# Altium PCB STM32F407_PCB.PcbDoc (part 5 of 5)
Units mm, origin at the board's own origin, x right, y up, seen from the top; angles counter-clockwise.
Board outline 100.27 x 100.27 mm, 2 copper layers (Top Layer, Bottom Layer); 134 components, 132 nets, 659 pads, 288 vias.
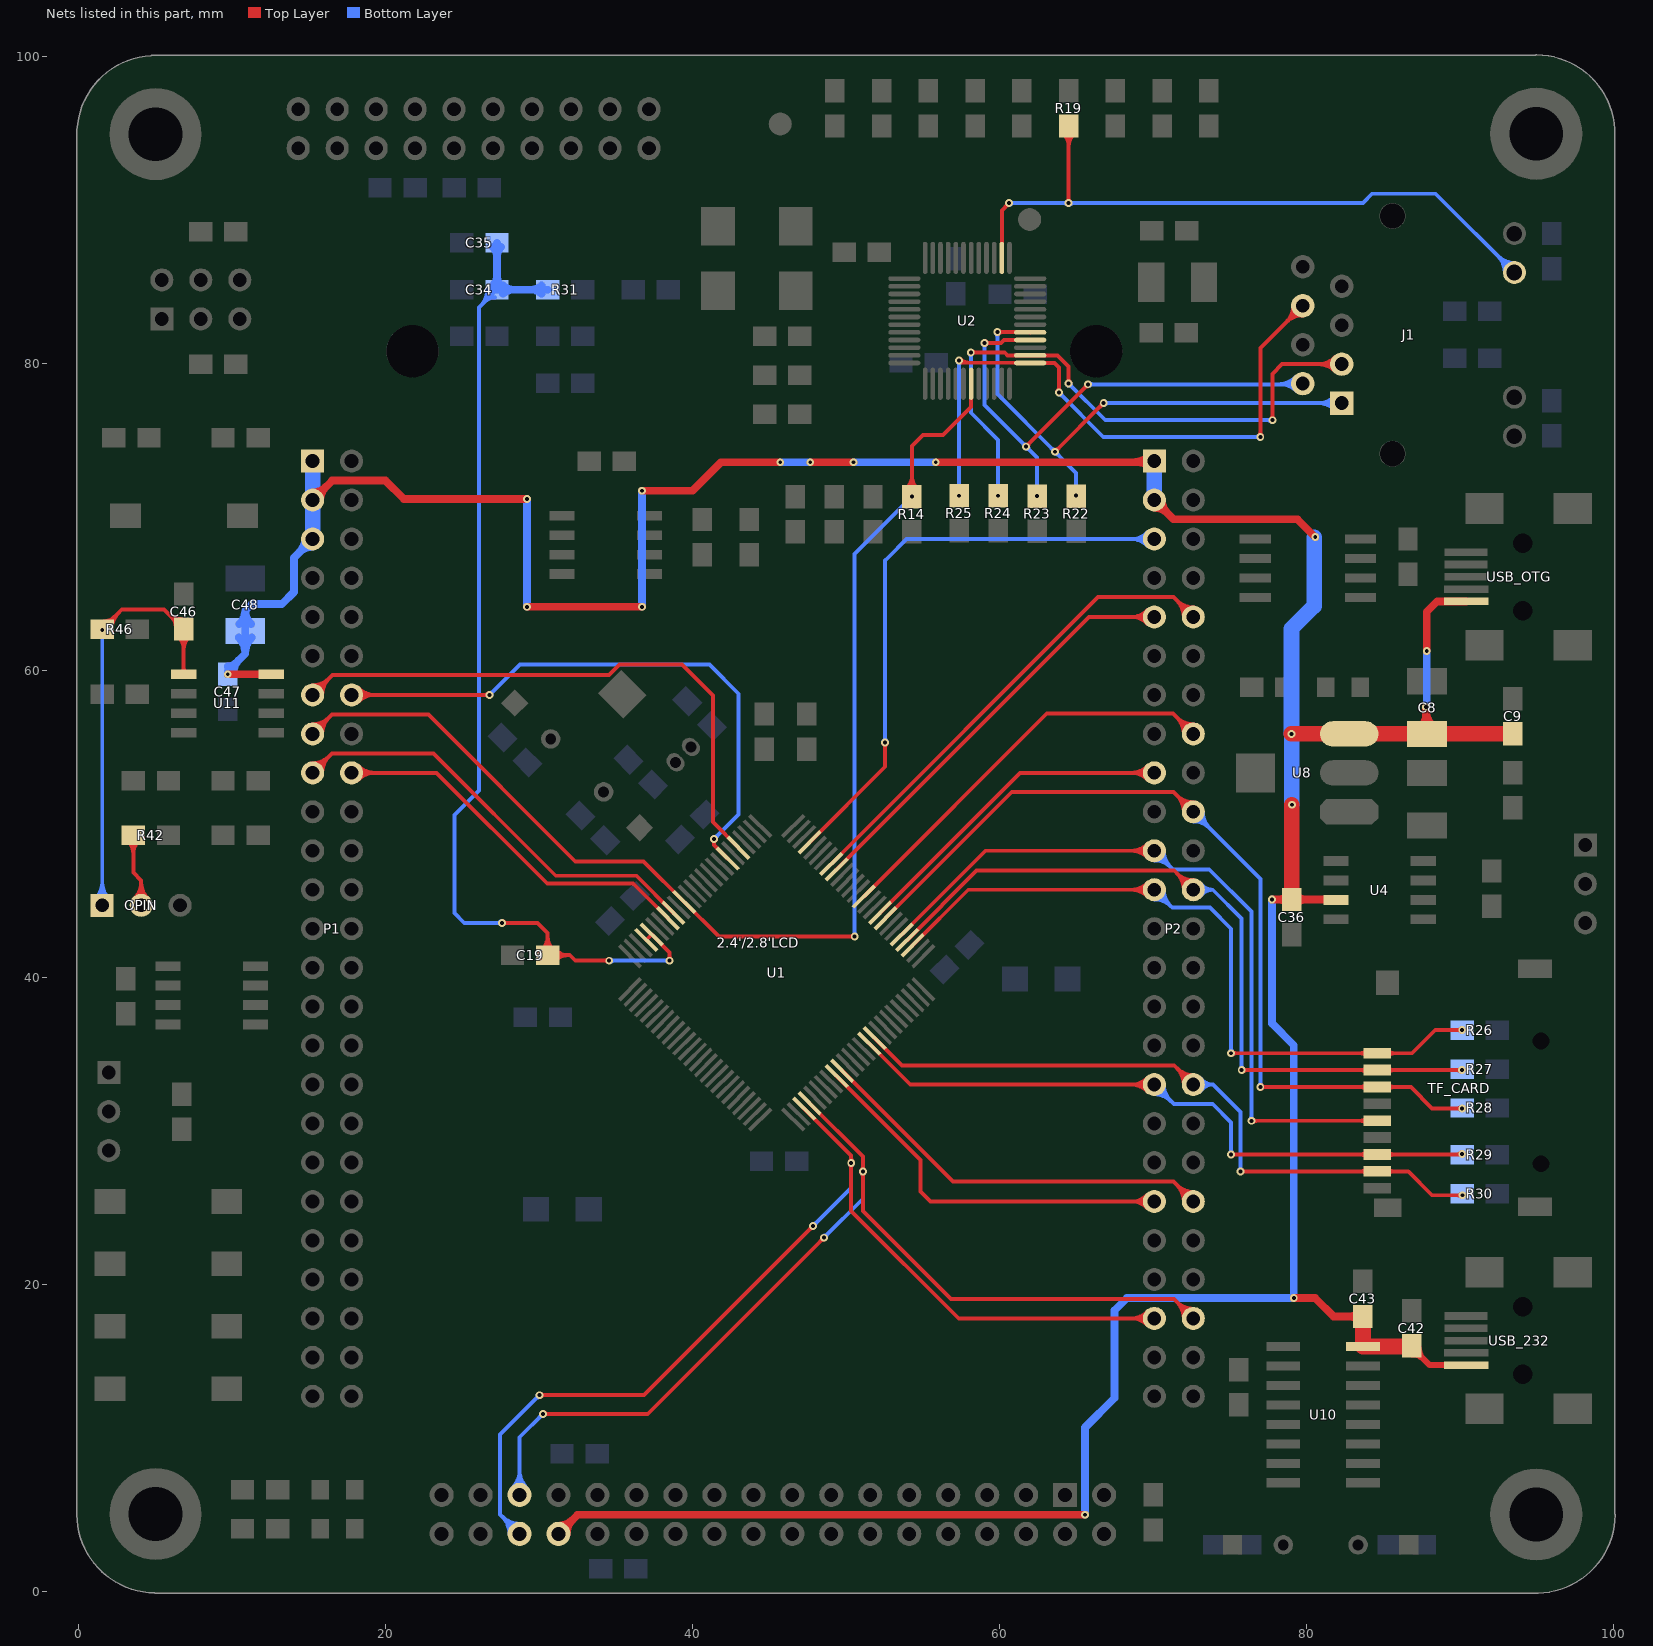
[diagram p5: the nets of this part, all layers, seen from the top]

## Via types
v1: diameter 0.508, hole 0.254, Top Layer to Bottom Layer, 288 vias

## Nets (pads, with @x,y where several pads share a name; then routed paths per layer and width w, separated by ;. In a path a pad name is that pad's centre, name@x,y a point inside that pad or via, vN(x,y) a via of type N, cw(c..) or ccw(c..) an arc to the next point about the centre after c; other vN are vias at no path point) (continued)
PB6: P2.9 U1.92 | length 35
  Top Layer w0.254: U1.92@49.398,47.045 65.853,63.5 P2.9@70.104,63.5 ; 68.6,63.5 cw(c68.6,61.996) 69.663,63.059 ccw(c68.6,61.996) 68.6,63.5 ; 68.6,63.5 ccw(c68.6,65.004) 69.663,63.941 cw(c68.6,65.004) 68.6,63.5 ; 69.213,63.5 cw(c69.213,62.609) 69.843,63.239 ccw(c69.213,62.609) 69.213,63.5 ; 69.213,63.5 ccw(c69.213,64.391) 69.843,63.761 cw(c69.213,64.391) 69.213,63.5
PB7: P2.10 U1.93 | length 38.9
  Top Layer w0.254: U1.93@49.045,47.399 66.441,64.795 71.349,64.795 P2.10@72.644,63.5 ; 71.58,64.564 cw(c70.517,63.5) 72.021,63.5 ccw(c70.517,63.5) 71.58,64.564 ; 71.58,64.564 ccw(c72.644,65.627) 72.644,64.123 cw(c72.644,65.627) 71.58,64.564 ; 72.014,64.13 cw(c71.384,63.5) 72.275,63.5 ccw(c71.384,63.5) 72.014,64.13 ; 72.014,64.13 ccw(c72.644,64.76) 72.644,63.869 cw(c72.644,64.76) 72.014,64.13
PB14: 2.4'/2.8'LCD.30 P2.45 U1.53 | length 91.1
  Top Layer w0.254: v1(30.023,12.776) 36.83,12.776 v1(47.854,23.8) ; U1.53@47.277,31.453 50.343,28.387 v1(50.343,27.915) 50.343,24.79 57.353,17.78 P2.45@70.104,17.78 ; 30.329,12.776 cw(c30.329,13.083) 30.113,12.866 ccw(c30.329,13.083) 30.329,12.776 ; 30.329,12.776 ccw(c30.329,12.47) 30.113,12.686 cw(c30.329,12.47) 30.329,12.776 ; 47.637,23.583 cw(c47.854,23.366) 47.854,23.673 ccw(c47.854,23.366) 47.637,23.583 ; 47.637,23.583 ccw(c47.42,23.8) 47.727,23.8 cw(c47.42,23.8) 47.637,23.583 ; 50.343,27.608 cw(c50.649,27.608) 50.433,27.825 ccw(c50.649,27.608) 50.343,27.608 ; 50.343,27.608 ccw(c50.036,27.608) 50.253,27.825 cw(c50.036,27.608) 50.343,27.608 ; 50.343,28.221 cw(c50.036,28.221) 50.253,28.004 ccw(c50.036,28.221) 50.343,28.221 ; 50.343,28.221 ccw(c50.649,28.221) 50.433,28.004 cw(c50.649,28.221) 50.343,28.221 ; 68.6,17.78 cw(c68.6,16.276) 69.663,17.339 ccw(c68.6,16.276) 68.6,17.78 ; 68.6,17.78 ccw(c68.6,19.284) 69.663,18.221 cw(c68.6,19.284) 68.6,17.78 ; 69.213,17.78 cw(c69.213,16.889) 69.843,17.519 ccw(c69.213,16.889) 69.213,17.78 ; 69.213,17.78 ccw(c69.213,18.671) 69.843,18.041 cw(c69.213,18.671) 69.213,17.78
  Bottom Layer w0.254: 2.4'/2.8'LCD.30@28.727,3.734 27.457,5.004 27.457,10.211 v1(30.023,12.776) ; v1(47.854,23.8) 50.343,26.289 v1(50.343,27.915) ; 27.6,4.861 cw(c26.473,3.734) 28.067,3.734 ccw(c26.473,3.734) 27.6,4.861 ; 27.6,4.861 ccw(c28.727,5.989) 28.727,4.394 cw(c28.727,5.989) 27.6,4.861 ; 28.034,4.428 cw(c27.34,3.734) 28.321,3.734 ccw(c27.34,3.734) 28.034,4.428 ; 28.034,4.428 ccw(c28.727,5.121) 28.727,4.14 cw(c28.727,5.121) 28.034,4.428 ; 29.806,12.559 cw(c30.023,12.343) 30.023,12.649 ccw(c30.023,12.343) 29.806,12.559 ; 29.806,12.559 ccw(c29.589,12.776) 29.896,12.776 cw(c29.589,12.776) 29.806,12.559 ; 48.07,24.017 cw(c47.854,24.233) 47.854,23.927 ccw(c47.854,24.233) 48.07,24.017 ; 48.07,24.017 ccw(c48.287,23.8) 47.981,23.8 cw(c48.287,23.8) 48.07,24.017 ; 50.343,27.608 cw(c50.649,27.608) 50.433,27.825 ccw(c50.649,27.608) 50.343,27.608 ; 50.343,27.608 ccw(c50.036,27.608) 50.253,27.825 cw(c50.036,27.608) 50.343,27.608
PB15: 2.4'/2.8'LCD.29 P2.46 U1.54 | length 89.6
  Top Layer w0.254: v1(30.251,11.557) 37.084,11.557 v1@48.489,22.962 ; U1.54@47.63,31.807 51.105,28.332 v1(51.105,27.356) 51.105,24.79 56.845,19.05 71.374,19.05 P2.46@72.644,17.78 ; 30.558,11.557 cw(c30.558,11.864) 30.341,11.647 ccw(c30.558,11.864) 30.558,11.557 ; 30.558,11.557 ccw(c30.558,11.25) 30.341,11.467 cw(c30.558,11.25) 30.558,11.557 ; 48.351,22.824 cw(c48.568,22.607) 48.568,22.914 ccw(c48.568,22.607) 48.351,22.824 ; 48.351,22.824 ccw(c48.134,23.041) 48.441,23.041 cw(c48.134,23.041) 48.351,22.824 ; 51.105,27.049 cw(c51.411,27.049) 51.195,27.266 ccw(c51.411,27.049) 51.105,27.049 ; 51.105,27.049 ccw(c50.798,27.049) 51.015,27.266 cw(c50.798,27.049) 51.105,27.049 ; 51.105,27.662 cw(c50.798,27.662) 51.015,27.446 ccw(c50.798,27.662) 51.105,27.662 ; 51.105,27.662 ccw(c51.411,27.662) 51.195,27.446 cw(c51.411,27.662) 51.105,27.662 ; 71.58,18.844 cw(c70.517,17.78) 72.021,17.78 ccw(c70.517,17.78) 71.58,18.844 ; 71.58,18.844 ccw(c72.644,19.907) 72.644,18.403 cw(c72.644,19.907) 71.58,18.844 ; 72.014,18.41 cw(c71.384,17.78) 72.275,17.78 ccw(c71.384,17.78) 72.014,18.41 ; 72.014,18.41 ccw(c72.644,19.04) 72.644,18.149 cw(c72.644,19.04) 72.014,18.41
  Bottom Layer w0.254: 2.4'/2.8'LCD.29@28.727,6.274 28.727,10.033 v1(30.251,11.557) ; v1@48.489,22.962 v1(48.568,23.041) 51.105,25.578 v1(51.105,27.356) ; 28.727,7.255 cw(c27.746,7.255) 28.44,6.561 ccw(c27.746,7.255) 28.727,7.255 ; 28.727,7.255 ccw(c29.709,7.255) 29.015,6.561 cw(c29.709,7.255) 28.727,7.255 ; 28.727,7.868 cw(c27.133,7.868) 28.26,6.741 ccw(c27.133,7.868) 28.727,7.868 ; 28.727,7.868 ccw(c30.322,7.868) 29.194,6.741 cw(c30.322,7.868) 28.727,7.868 ; 30.035,11.34 cw(c30.251,11.123) 30.251,11.43 ccw(c30.251,11.123) 30.035,11.34 ; 30.035,11.34 ccw(c29.818,11.557) 30.124,11.557 cw(c29.818,11.557) 30.035,11.34 ; 48.785,23.258 cw(c48.568,23.475) 48.568,23.168 ccw(c48.568,23.475) 48.785,23.258 ; 48.785,23.258 ccw(c49.002,23.041) 48.695,23.041 cw(c49.002,23.041) 48.785,23.258 ; 51.105,27.049 cw(c51.411,27.049) 51.195,27.266 ccw(c51.411,27.049) 51.105,27.049 ; 51.105,27.049 ccw(c50.798,27.049) 51.015,27.266 cw(c50.798,27.049) 51.105,27.049
PC0: P1.15 R14.2 U1.15 U2.7 | length 97
  Top Layer w0.254: P1.15@15.24,55.88 16.51,57.15 22.784,57.15 32.36,47.574 36.813,47.574 U1.15@39.463,44.924 41.715,42.672 v1(50.571,42.672) ; v1(54.305,71.349) 54.305,74.651 55.016,75.362 56.337,75.362 58.162,77.187 U2.7@58.162,78.704 ; 15.87,56.51 cw(c15.24,57.14) 15.24,56.249 ccw(c15.24,57.14) 15.87,56.51 ; 15.87,56.51 ccw(c16.5,55.88) 15.609,55.88 cw(c16.5,55.88) 15.87,56.51 ; 16.304,56.944 cw(c15.24,58.007) 15.24,56.503 ccw(c15.24,58.007) 16.304,56.944 ; 16.304,56.944 ccw(c17.367,55.88) 15.863,55.88 cw(c17.367,55.88) 16.304,56.944 ; 50.265,42.672 cw(c50.265,42.365) 50.482,42.582 ccw(c50.265,42.365) 50.265,42.672 ; 50.265,42.672 ccw(c50.265,42.979) 50.482,42.762 cw(c50.265,42.979) 50.265,42.672 ; R14.2@54.305,71.655 cw(c53.999,71.655) 54.215,71.438 ccw(c53.999,71.655) R14.2@54.305,71.655 ; R14.2@54.305,71.655 ccw(c54.612,71.655) 54.395,71.438 cw(c54.612,71.655) R14.2@54.305,71.655 ; 54.305,72.702 cw(c53.079,72.702) 53.946,71.835 ccw(c53.079,72.702) 54.305,72.702 ; 54.305,72.702 ccw(c55.532,72.702) 54.664,71.835 cw(c55.532,72.702) 54.305,72.702
  Bottom Layer w0.254: v1(50.571,42.672) 50.571,67.615 v1(54.305,71.349) ; 50.571,42.979 cw(c50.265,42.979) 50.482,42.762 ccw(c50.265,42.979) 50.571,42.979 ; 50.571,42.979 ccw(c50.878,42.979) 50.661,42.762 cw(c50.878,42.979) 50.571,42.979 ; 54.088,71.132 cw(c54.305,70.915) 54.305,71.222 ccw(c54.305,70.915) 54.088,71.132 ; 54.088,71.132 ccw(c53.872,71.349) 54.178,71.349 cw(c53.872,71.349) 54.088,71.132
PC2: P1.17 U1.17 | length 35.9
  Top Layer w0.254: P1.17@15.24,53.34 16.51,54.61 23.114,54.61 31.09,46.634 36.338,46.634 U1.17@38.756,44.217 ; 15.87,53.97 cw(c15.24,54.6) 15.24,53.709 ccw(c15.24,54.6) 15.87,53.97 ; 15.87,53.97 ccw(c16.5,53.34) 15.609,53.34 cw(c16.5,53.34) 15.87,53.97 ; 16.304,54.404 cw(c15.24,55.467) 15.24,53.963 ccw(c15.24,55.467) 16.304,54.404 ; 16.304,54.404 ccw(c17.367,53.34) 15.863,53.34 cw(c17.367,53.34) 16.304,54.404
PC3: P1.18 U1.18 | length 32.1
  Top Layer w0.254: P1.18@17.78,53.34 23.317,53.34 30.531,46.126 36.139,46.126 U1.18@38.403,43.863 ; 18.671,53.34 cw(c18.671,54.231) 18.041,53.601 ccw(c18.671,54.231) 18.671,53.34 ; 18.671,53.34 ccw(c18.671,52.449) 18.041,53.079 cw(c18.671,52.449) 18.671,53.34 ; 19.284,53.34 cw(c19.284,54.844) 18.221,53.781 ccw(c19.284,54.844) 19.284,53.34 ; 19.284,53.34 ccw(c19.284,51.836) 18.221,52.899 cw(c19.284,51.836) 19.284,53.34
PC8: P2.33 R29.2 TF_CARD.7 U1.65 | length 63.9
  Top Layer w0.254: U1.65@51.519,35.696 54.195,33.02 P2.33@70.104,33.02 ; v1(75.108,28.464) TF_CARD.7@84.633,28.464 90.135,28.464 v1(90.17,28.499) ; 68.6,33.02 cw(c68.6,31.516) 69.663,32.579 ccw(c68.6,31.516) 68.6,33.02 ; 68.6,33.02 ccw(c68.6,34.524) 69.663,33.461 cw(c68.6,34.524) 68.6,33.02 ; 69.213,33.02 cw(c69.213,32.129) 69.843,32.759 ccw(c69.213,32.129) 69.213,33.02 ; 69.213,33.02 ccw(c69.213,33.911) 69.843,33.281 cw(c69.213,33.911) 69.213,33.02 ; 75.414,28.464 cw(c75.414,28.77) 75.198,28.553 ccw(c75.414,28.77) 75.414,28.464 ; 75.414,28.464 ccw(c75.414,28.157) 75.198,28.374 cw(c75.414,28.157) 75.414,28.464 ; 83.544,28.464 cw(c83.544,27.925) 83.925,28.306 ccw(c83.544,27.925) 83.544,28.464 ; 83.544,28.464 ccw(c83.544,29.002) 83.925,28.621 cw(c83.544,29.002) 83.544,28.464 ; 85.721,28.464 cw(c85.721,29.002) 85.34,28.621 ccw(c85.721,29.002) 85.721,28.464 ; 85.721,28.464 ccw(c85.721,27.925) 85.34,28.306 cw(c85.721,27.925) 85.721,28.464 ; 89.778,28.464 ccw(c89.778,28.89) 90.08,28.589 cw(c89.778,28.89) 89.778,28.464
  Bottom Layer w0.254: P2.33@70.104,33.02 71.374,31.75 73.914,31.75 75.108,30.556 v1(75.108,28.464) ; 70.734,32.39 cw(c71.364,33.02) 70.473,33.02 ccw(c71.364,33.02) 70.734,32.39 ; 70.734,32.39 ccw(c70.104,31.76) 70.104,32.651 cw(c70.104,31.76) 70.734,32.39 ; 71.168,31.956 cw(c72.231,33.02) 70.727,33.02 ccw(c72.231,33.02) 71.168,31.956 ; 71.168,31.956 ccw(c70.104,30.893) 70.104,32.397 cw(c70.104,30.893) 71.168,31.956 ; 75.108,28.77 cw(c74.801,28.77) 75.018,28.553 ccw(c74.801,28.77) 75.108,28.77 ; 75.108,28.77 ccw(c75.414,28.77) 75.198,28.553 cw(c75.414,28.77) 75.108,28.77
PC9: P2.34 R30.2 TF_CARD.8 U1.66 | length 64.5
  Top Layer w0.254: U1.66@51.873,36.049 53.658,34.265 71.399,34.265 P2.34@72.644,33.02 ; v1(75.717,27.364) TF_CARD.8@84.633,27.364 86.657,27.364 88.214,25.806 v1(90.195,25.806) ; 71.58,34.084 cw(c70.517,33.02) 72.021,33.02 ccw(c70.517,33.02) 71.58,34.084 ; 71.58,34.084 ccw(c72.644,35.147) 72.644,33.643 cw(c72.644,35.147) 71.58,34.084 ; 72.014,33.65 cw(c71.384,33.02) 72.275,33.02 ccw(c71.384,33.02) 72.014,33.65 ; 72.014,33.65 ccw(c72.644,34.28) 72.644,33.389 cw(c72.644,34.28) 72.014,33.65 ; 76.024,27.364 cw(c76.024,27.67) 75.807,27.453 ccw(c76.024,27.67) 76.024,27.364 ; 76.024,27.364 ccw(c76.024,27.057) 75.807,27.274 cw(c76.024,27.057) 76.024,27.364 ; 83.544,27.364 cw(c83.544,26.825) 83.925,27.206 ccw(c83.544,26.825) 83.544,27.364 ; 83.544,27.364 ccw(c83.544,27.902) 83.925,27.521 cw(c83.544,27.902) 83.544,27.364 ; 85.721,27.364 cw(c85.721,27.902) 85.34,27.521 ccw(c85.721,27.902) 85.721,27.364 ; 85.721,27.364 ccw(c85.721,26.825) 85.34,27.206 cw(c85.721,26.825) 85.721,27.364 ; 89.889,25.806 cw(c89.889,25.5) 90.106,25.717 ccw(c89.889,25.5) 89.889,25.806 ; 89.889,25.806 ccw(c89.889,26.113) 90.106,25.896 cw(c89.889,26.113) 89.889,25.806
  Bottom Layer w0.254: P2.34@72.644,33.02 73.939,33.02 ; v1(75.717,27.364) 75.717,31.242 73.939,33.02 ; 73.411,33.02 cw(c73.411,33.633) 72.932,33.25 ccw(c73.411,33.633) 73.411,33.02 ; 73.411,33.02 ccw(c73.411,32.407) 72.932,32.79 cw(c73.411,32.407) 73.411,33.02 ; 73.939,33.02 cw(c73.939,34.055) 73.131,33.409 ccw(c73.939,34.055) 73.939,33.02 ; 73.939,33.02 ccw(c73.939,31.985) 73.131,32.631 cw(c73.939,31.985) 73.939,33.02 ; 75.717,27.67 cw(c75.411,27.67) 75.628,27.453 ccw(c75.411,27.67) 75.717,27.67 ; 75.717,27.67 ccw(c76.024,27.67) 75.807,27.453 cw(c76.024,27.67) 75.717,27.67
PC10: P2.23 R26.2 TF_CARD.1 U1.78 | length 68.4
  Top Layer w0.254: U1.78@54.348,42.095 57.973,45.72 P2.23@70.104,45.72 ; v1(75.108,35.064) TF_CARD.1@84.633,35.064 86.905,35.064 88.416,36.574 v1(90.17,36.574) ; 68.6,45.72 cw(c68.6,44.216) 69.663,45.279 ccw(c68.6,44.216) 68.6,45.72 ; 68.6,45.72 ccw(c68.6,47.224) 69.663,46.161 cw(c68.6,47.224) 68.6,45.72 ; 69.213,45.72 cw(c69.213,44.829) 69.843,45.459 ccw(c69.213,44.829) 69.213,45.72 ; 69.213,45.72 ccw(c69.213,46.611) 69.843,45.981 cw(c69.213,46.611) 69.213,45.72 ; 75.414,35.064 cw(c75.414,35.37) 75.198,35.153 ccw(c75.414,35.37) 75.414,35.064 ; 75.414,35.064 ccw(c75.414,34.757) 75.198,34.974 cw(c75.414,34.757) 75.414,35.064 ; 83.544,35.064 cw(c83.544,34.525) 83.925,34.906 ccw(c83.544,34.525) 83.544,35.064 ; 83.544,35.064 ccw(c83.544,35.602) 83.925,35.221 cw(c83.544,35.602) 83.544,35.064 ; 85.721,35.064 cw(c85.721,35.602) 85.34,35.221 ccw(c85.721,35.602) 85.721,35.064 ; 85.721,35.064 ccw(c85.721,34.525) 85.34,34.906 cw(c85.721,34.525) 85.721,35.064 ; 89.863,36.574 cw(c89.863,36.268) 90.08,36.485 ccw(c89.863,36.268) 89.863,36.574 ; 89.863,36.574 ccw(c89.863,36.881) 90.08,36.664 cw(c89.863,36.881) 89.863,36.574
  Bottom Layer w0.254: P2.23@70.104,45.72 71.272,44.552 73.736,44.552 75.108,43.18 v1(75.108,35.064) ; 70.734,45.09 cw(c71.364,45.72) 70.473,45.72 ccw(c71.364,45.72) 70.734,45.09 ; 70.734,45.09 ccw(c70.104,44.46) 70.104,45.351 cw(c70.104,44.46) 70.734,45.09 ; 71.168,44.656 cw(c72.231,45.72) 70.727,45.72 ccw(c72.231,45.72) 71.168,44.656 ; 71.168,44.656 ccw(c70.104,43.593) 70.104,45.097 cw(c70.104,43.593) 71.168,44.656 ; 75.108,35.37 cw(c74.801,35.37) 75.018,35.153 ccw(c74.801,35.37) 75.108,35.37 ; 75.108,35.37 ccw(c75.414,35.37) 75.198,35.153 cw(c75.414,35.37) 75.108,35.37
PC11: P2.24 R27.2 TF_CARD.2 U1.79 | length 68.7
  Top Layer w0.254: U1.79@53.994,42.449 54.006,42.449 58.522,46.965 71.399,46.965 P2.24@72.644,45.72 ; v1(75.797,33.964) TF_CARD.2@84.633,33.964 v1(90.148,33.964) ; 71.58,46.784 cw(c70.517,45.72) 72.021,45.72 ccw(c70.517,45.72) 71.58,46.784 ; 71.58,46.784 ccw(c72.644,47.847) 72.644,46.343 cw(c72.644,47.847) 71.58,46.784 ; 72.014,46.35 cw(c71.384,45.72) 72.275,45.72 ccw(c71.384,45.72) 72.014,46.35 ; 72.014,46.35 ccw(c72.644,46.98) 72.644,46.089 cw(c72.644,46.98) 72.014,46.35 ; 76.104,33.964 cw(c76.104,34.27) 75.887,34.053 ccw(c76.104,34.27) 76.104,33.964 ; 76.104,33.964 ccw(c76.104,33.657) 75.887,33.874 cw(c76.104,33.657) 76.104,33.964 ; 83.544,33.964 cw(c83.544,33.425) 83.925,33.806 ccw(c83.544,33.425) 83.544,33.964 ; 83.544,33.964 ccw(c83.544,34.502) 83.925,34.121 cw(c83.544,34.502) 83.544,33.964 ; 85.721,33.964 cw(c85.721,34.502) 85.34,34.121 ccw(c85.721,34.502) 85.721,33.964 ; 85.721,33.964 ccw(c85.721,33.425) 85.34,33.806 cw(c85.721,33.425) 85.721,33.964 ; 89.842,33.964 cw(c89.842,33.657) 90.059,33.874 ccw(c89.842,33.657) 89.842,33.964 ; 89.842,33.964 ccw(c89.842,34.27) 90.059,34.053 cw(c89.842,34.27) 89.842,33.964
  Bottom Layer w0.254: P2.24@72.644,45.72 73.914,45.72 ; v1(75.797,33.964) 75.797,43.837 73.914,45.72 ; 73.396,45.72 cw(c73.396,46.302) 72.936,45.946 ccw(c73.396,46.302) 73.396,45.72 ; 73.396,45.72 ccw(c73.396,45.138) 72.936,45.494 cw(c73.396,45.138) 73.396,45.72 ; 73.914,45.72 cw(c73.914,46.703) 73.137,46.101 ccw(c73.914,46.703) 73.914,45.72 ; 73.914,45.72 ccw(c73.914,44.737) 73.137,45.339 cw(c73.914,44.737) 73.914,45.72 ; 75.797,34.27 cw(c75.491,34.27) 75.708,34.053 ccw(c75.491,34.27) 75.797,34.27 ; 75.797,34.27 ccw(c76.104,34.27) 75.887,34.053 cw(c76.104,34.27) 75.797,34.27
PC12: P2.21 TF_CARD.5 U1.80 | length 67.2
  Top Layer w0.254: U1.80@53.641,42.802 59.098,48.26 P2.21@70.104,48.26 ; v1(76.429,30.658) TF_CARD.5@84.633,30.664 ; 68.6,48.26 cw(c68.6,46.756) 69.663,47.819 ccw(c68.6,46.756) 68.6,48.26 ; 68.6,48.26 ccw(c68.6,49.764) 69.663,48.701 cw(c68.6,49.764) 68.6,48.26 ; 69.213,48.26 cw(c69.213,47.369) 69.843,47.999 ccw(c69.213,47.369) 69.213,48.26 ; 69.213,48.26 ccw(c69.213,49.151) 69.843,48.521 cw(c69.213,49.151) 69.213,48.26 ; 76.735,30.658 cw(c76.735,30.965) 76.518,30.748 ccw(c76.735,30.965) 76.735,30.658 ; 76.735,30.658 ccw(c76.735,30.351) 76.518,30.568 cw(c76.735,30.351) 76.735,30.658 ; 83.543,30.663 ccw(c83.543,31.203) 83.925,30.821 cw(c83.543,31.203) 83.543,30.663 ; 83.545,30.663 cw(c83.546,30.126) 83.925,30.506 ccw(c83.546,30.126) 83.545,30.663
  Bottom Layer w0.254: P2.21@70.104,48.26 71.323,47.041 73.685,47.041 76.429,44.298 v1(76.429,30.658) ; 70.734,47.63 cw(c71.364,48.26) 70.473,48.26 ccw(c71.364,48.26) 70.734,47.63 ; 70.734,47.63 ccw(c70.104,47) 70.104,47.891 cw(c70.104,47) 70.734,47.63 ; 71.168,47.196 cw(c72.231,48.26) 70.727,48.26 ccw(c72.231,48.26) 71.168,47.196 ; 71.168,47.196 ccw(c70.104,46.133) 70.104,47.637 cw(c70.104,46.133) 71.168,47.196 ; 76.429,30.964 cw(c76.122,30.964) 76.339,30.748 ccw(c76.122,30.964) 76.429,30.964 ; 76.429,30.964 ccw(c76.735,30.964) 76.518,30.748 cw(c76.735,30.964) 76.429,30.964
PC13: P1.14 U1.7 | length 50.9
  Top Layer w0.254: P1.14@17.78,58.42 v1(26.772,58.42) ; v1(41.402,49.022) 41.402,48.642 U1.7@42.292,47.752 ; 18.671,58.42 cw(c18.671,59.311) 18.041,58.681 ccw(c18.671,59.311) 18.671,58.42 ; 18.671,58.42 ccw(c18.671,57.529) 18.041,58.159 cw(c18.671,57.529) 18.671,58.42 ; 19.284,58.42 cw(c19.284,59.924) 18.221,58.861 ccw(c19.284,59.924) 19.284,58.42 ; 19.284,58.42 ccw(c19.284,56.916) 18.221,57.979 cw(c19.284,56.916) 19.284,58.42 ; 26.465,58.42 cw(c26.465,58.113) 26.682,58.33 ccw(c26.465,58.113) 26.465,58.42 ; 26.465,58.42 ccw(c26.465,58.727) 26.682,58.51 cw(c26.465,58.727) 26.465,58.42 ; v1@41.312,48.932 cw(c41.095,48.715) 41.402,48.715 ; v1@41.312,48.932 cw(c41.095,48.715) 41.402,48.715 ; v1@41.312,48.932 cw(c41.095,48.715) 41.402,48.715 ; v1@41.312,48.932 cw(c41.095,48.715) 41.402,48.715 ; 41.402,48.715 cw(c41.709,48.715) v1@41.492,48.932 ; 41.402,48.715 cw(c41.709,48.715) v1@41.492,48.932 ; 41.402,48.715 cw(c41.709,48.715) v1@41.492,48.932 ; 41.402,48.715 cw(c41.709,48.715) v1@41.492,48.932
  Bottom Layer w0.254: v1(26.772,58.42) 28.753,60.401 41.097,60.401 43.002,58.496 43.002,50.622 v1(41.402,49.022) ; 26.988,58.637 cw(c26.772,58.854) 26.772,58.547 ccw(c26.772,58.854) 26.988,58.637 ; 26.988,58.637 ccw(c27.205,58.42) 26.899,58.42 cw(c27.205,58.42) 26.988,58.637 ; 41.619,49.239 cw(c41.402,49.456) 41.402,49.149 ccw(c41.402,49.456) 41.619,49.239 ; 41.619,49.239 ccw(c41.836,49.022) 41.529,49.022 cw(c41.836,49.022) 41.619,49.239
PD2: P2.20 R28.2 TF_CARD.3 U1.83 | length 79
  Top Layer w0.254: U1.83@52.58,43.863 60.813,52.095 71.349,52.095 P2.20@72.644,50.8 ; v1(77.013,32.864) TF_CARD.3@84.633,32.864 86.821,32.864 88.214,31.471 v1(90.17,31.471) ; 71.58,51.864 cw(c70.517,50.8) 72.021,50.8 ccw(c70.517,50.8) 71.58,51.864 ; 71.58,51.864 ccw(c72.644,52.927) 72.644,51.423 cw(c72.644,52.927) 71.58,51.864 ; 72.014,51.43 cw(c71.384,50.8) 72.275,50.8 ccw(c71.384,50.8) 72.014,51.43 ; 72.014,51.43 ccw(c72.644,52.06) 72.644,51.169 cw(c72.644,52.06) 72.014,51.43 ; 77.319,32.864 cw(c77.319,33.17) 77.103,32.953 ccw(c77.319,33.17) 77.319,32.864 ; 77.319,32.864 ccw(c77.319,32.557) 77.103,32.774 cw(c77.319,32.557) 77.319,32.864 ; 83.544,32.864 cw(c83.544,32.325) 83.925,32.706 ccw(c83.544,32.325) 83.544,32.864 ; 83.544,32.864 ccw(c83.544,33.402) 83.925,33.021 cw(c83.544,33.402) 83.544,32.864 ; 85.721,32.864 cw(c85.721,33.402) 85.34,33.021 ccw(c85.721,33.402) 85.721,32.864 ; 85.721,32.864 ccw(c85.721,32.325) 85.34,32.706 cw(c85.721,32.325) 85.721,32.864 ; 89.863,31.471 cw(c89.863,31.164) 90.08,31.381 ccw(c89.863,31.164) 89.863,31.471 ; 89.863,31.471 ccw(c89.863,31.777) 90.08,31.56 cw(c89.863,31.777) 89.863,31.471
  Bottom Layer w0.254: P2.20@72.644,50.8 77.013,46.431 v1(77.013,32.864) ; P2.20@72.707,50.635 P2.20@72.707,50.863 ; 73.274,50.17 cw(c73.904,50.8) 73.013,50.8 ccw(c73.904,50.8) 73.274,50.17 ; 73.274,50.17 ccw(c72.644,49.54) 72.644,50.431 cw(c72.644,49.54) 73.274,50.17 ; 73.708,49.736 cw(c74.771,50.8) 73.267,50.8 ccw(c74.771,50.8) 73.708,49.736 ; 73.708,49.736 ccw(c72.644,48.673) 72.644,50.177 cw(c72.644,48.673) 73.708,49.736 ; 77.013,33.17 cw(c76.706,33.17) 76.923,32.953 ccw(c76.706,33.17) 77.013,33.17 ; 77.013,33.17 ccw(c77.319,33.17) 77.103,32.953 cw(c77.319,33.17) 77.013,33.17
PD3: P2.17 U1.84 | length 29.2
  Top Layer w0.254: U1.84@52.227,44.217 61.35,53.34 P2.17@70.104,53.34 ; 68.6,53.34 cw(c68.6,51.836) 69.663,52.899 ccw(c68.6,51.836) 68.6,53.34 ; 68.6,53.34 ccw(c68.6,54.844) 69.663,53.781 cw(c68.6,54.844) 68.6,53.34 ; 69.213,53.34 cw(c69.213,52.449) 69.843,53.079 ccw(c69.213,52.449) 69.213,53.34 ; 69.213,53.34 ccw(c69.213,54.231) 69.843,53.601 cw(c69.213,54.231) 69.213,53.34
PD6: P2.16 U1.87 | length 34.5
  Top Layer w0.254: U1.87@51.166,45.277 63.089,57.201 71.323,57.201 P2.16@72.644,55.88 ; 71.58,56.944 cw(c70.517,55.88) 72.021,55.88 ccw(c70.517,55.88) 71.58,56.944 ; 71.58,56.944 ccw(c72.644,58.007) 72.644,56.503 cw(c72.644,58.007) 71.58,56.944 ; 72.014,56.51 cw(c71.384,55.88) 72.275,55.88 ccw(c71.384,55.88) 72.014,56.51 ; 72.014,56.51 ccw(c72.644,57.14) 72.644,56.249 cw(c72.644,57.14) 72.014,56.51
PD12: P2.39 U1.59 | length 32.8
  Top Layer w0.254: U1.59@49.398,33.575 54.864,28.109 54.864,26.06 55.524,25.4 P2.39@70.104,25.4 ; 68.6,25.4 cw(c68.6,23.896) 69.663,24.959 ccw(c68.6,23.896) 68.6,25.4 ; 68.6,25.4 ccw(c68.6,26.904) 69.663,25.841 cw(c68.6,26.904) 68.6,25.4 ; 69.213,25.4 cw(c69.213,24.509) 69.843,25.139 ccw(c69.213,24.509) 69.213,25.4 ; 69.213,25.4 ccw(c69.213,26.291) 69.843,25.661 cw(c69.213,26.291) 69.213,25.4
PD13: P2.40 U1.60 | length 33.9
  Top Layer w0.254: U1.60@49.752,33.928 56.984,26.695 71.349,26.695 P2.40@72.644,25.4 ; 71.58,26.464 cw(c70.517,25.4) 72.021,25.4 ccw(c70.517,25.4) 71.58,26.464 ; 71.58,26.464 ccw(c72.644,27.527) 72.644,26.023 cw(c72.644,27.527) 71.58,26.464 ; 72.014,26.03 cw(c71.384,25.4) 72.275,25.4 ccw(c71.384,25.4) 72.014,26.03 ; 72.014,26.03 ccw(c72.644,26.66) 72.644,25.769 cw(c72.644,26.66) 72.014,26.03
PE0: P2.5 U1.97 | length 48
  Top Layer w0.254: U1.97@47.63,48.813 52.553,53.735 v1(52.553,55.321) ; 52.553,55.015 cw(c52.859,55.015) 52.642,55.231 ccw(c52.859,55.015) 52.553,55.015 ; 52.553,55.015 ccw(c52.246,55.015) 52.463,55.231 cw(c52.246,55.015) 52.553,55.015
  Bottom Layer w0.254: v1(52.553,55.321) 52.553,67.183 52.73,67.361 53.95,68.58 P2.5@70.104,68.58 ; 52.553,55.628 cw(c52.246,55.628) 52.463,55.411 ccw(c52.246,55.628) 52.553,55.628 ; 52.553,55.628 ccw(c52.859,55.628) 52.642,55.411 cw(c52.859,55.628) 52.553,55.628 ; 68.6,68.58 cw(c68.6,67.076) 69.663,68.139 ccw(c68.6,67.076) 68.6,68.58 ; 68.6,68.58 ccw(c68.6,70.084) 69.663,69.021 cw(c68.6,70.084) 68.6,68.58 ; 69.213,68.58 cw(c69.213,67.689) 69.843,68.319 ccw(c69.213,67.689) 69.213,68.58 ; 69.213,68.58 ccw(c69.213,69.471) 69.843,68.841 cw(c69.213,69.471) 69.213,68.58
PE6: P1.13 U1.5 | length 45.9
  Top Layer w0.254: P1.13@15.24,58.42 16.535,59.715 34.553,59.715 35.229,60.392 39.303,60.392 41.326,58.369 41.326,50.132 U1.5@42.999,48.459 ; 15.87,59.05 cw(c15.24,59.68) 15.24,58.789 ccw(c15.24,59.68) 15.87,59.05 ; 15.87,59.05 ccw(c16.5,58.42) 15.609,58.42 cw(c16.5,58.42) 15.87,59.05 ; 16.304,59.484 cw(c15.24,60.547) 15.24,59.043 ccw(c15.24,60.547) 16.304,59.484 ; 16.304,59.484 ccw(c17.367,58.42) 15.863,58.42 cw(c17.367,58.42) 16.304,59.484
R-: J1.11 R19.1 U2.26 | length 60.3
  Top Layer w0.254: U2.26@60.162,86.904 60.162,90.007 v1(60.63,90.475) ; v1(64.516,90.475) 64.518,90.476 R19.1@64.518,95.504 ; 60.413,90.258 cw(c60.63,90.041) 60.63,90.348 ccw(c60.63,90.041) 60.413,90.258 ; 60.413,90.258 ccw(c60.196,90.475) 60.503,90.475 cw(c60.196,90.475) 60.413,90.258 ; 64.518,94.151 cw(c65.744,94.151) 64.877,95.018 ccw(c65.744,94.151) 64.518,94.151 ; 64.518,94.151 ccw(c63.291,94.151) 64.158,95.018 cw(c63.291,94.151) 64.518,94.151 ; v1@64.426,90.565 ccw(c64.205,90.785) 64.518,90.785 cw(c64.205,90.785) v1@64.426,90.565 ; 64.518,90.777 ccw(c64.819,90.777) 64.606,90.565 cw(c64.819,90.777) 64.518,90.777
  Bottom Layer w0.254: v1@60.604,90.475 v1(60.63,90.475) v1(64.516,90.475) 83.693,90.475 84.303,91.084 88.441,91.084 J1.11@93.571,85.954 ; 60.936,90.475 cw(c60.936,90.781) 60.72,90.565 ccw(c60.936,90.781) 60.936,90.475 ; 60.936,90.475 ccw(c60.936,90.168) 60.72,90.385 cw(c60.936,90.168) 60.936,90.475 ; 64.209,90.475 cw(c64.209,90.168) 64.426,90.385 ccw(c64.209,90.168) 64.209,90.475 ; 64.209,90.475 ccw(c64.209,90.781) 64.426,90.565 cw(c64.209,90.781) 64.209,90.475 ; 64.823,90.475 cw(c64.823,90.781) 64.606,90.565 ccw(c64.823,90.781) 64.823,90.475 ; 64.823,90.475 ccw(c64.823,90.168) 64.606,90.385 cw(c64.823,90.168) 64.823,90.475 ; 92.508,87.017 cw(c91.444,85.954) 92.948,85.954 ccw(c91.444,85.954) 92.508,87.017 ; 92.508,87.017 ccw(c93.571,88.081) 93.571,86.577 cw(c93.571,88.081) 92.508,87.017 ; 92.941,86.584 cw(c92.312,85.954) 93.202,85.954 ccw(c92.312,85.954) 92.941,86.584 ; 92.941,86.584 ccw(c93.571,87.213) 93.571,86.323 cw(c93.571,87.213) 92.941,86.584
RD+: J1.3 R24.2 U2.14 | length 54.5
  Top Layer w0.254: v1(58.141,80.747) 60.35,80.747 60.543,80.554 U2.14@62.012,80.554 63.789,80.554 64.516,79.827 v1(64.516,78.715) ; v1(77.8,76.327) 77.8,79.35 78.43,79.98 J1.3@82.321,79.98 ; 58.447,80.747 cw(c58.447,81.053) 58.23,80.836 ccw(c58.447,81.053) 58.447,80.747 ; 58.447,80.747 ccw(c58.447,80.44) 58.23,80.657 cw(c58.447,80.44) 58.447,80.747 ; 64.516,79.021 cw(c64.209,79.021) 64.426,78.804 ccw(c64.209,79.021) 64.516,79.021 ; 64.516,79.021 ccw(c64.823,79.021) 64.606,78.804 cw(c64.823,79.021) 64.516,79.021 ; 77.8,76.634 cw(c77.494,76.634) 77.71,76.417 ccw(c77.494,76.634) 77.8,76.634 ; 77.8,76.634 ccw(c78.107,76.634) 77.89,76.417 cw(c78.107,76.634) 77.8,76.634 ; 80.788,79.98 cw(c80.788,78.447) 81.872,79.531 ccw(c80.788,78.447) 80.788,79.98 ; 80.788,79.98 ccw(c80.788,81.513) 81.872,80.429 cw(c80.788,81.513) 80.788,79.98 ; 81.402,79.98 cw(c81.402,79.06) 82.052,79.71 ccw(c81.402,79.06) 81.402,79.98 ; 81.402,79.98 ccw(c81.402,80.899) 82.052,80.249 cw(c81.402,80.899) 81.402,79.98
  Bottom Layer w0.254: v1(58.141,80.747) 58.141,76.81 59.919,75.032 v1(59.919,71.399) ; v1(64.516,78.715) 66.904,76.327 v1(77.8,76.327) ; 58.141,80.44 cw(c58.447,80.44) 58.23,80.657 ccw(c58.447,80.44) 58.141,80.44 ; 58.141,80.44 ccw(c57.834,80.44) 58.051,80.657 cw(c57.834,80.44) 58.141,80.44 ; 59.919,71.706 cw(c59.612,71.706) 59.829,71.489 ccw(c59.612,71.706) 59.919,71.706 ; 59.919,71.706 ccw(c60.225,71.706) 60.008,71.489 cw(c60.225,71.706) 59.919,71.706 ; 64.733,78.498 cw(c64.95,78.715) 64.643,78.715 ccw(c64.95,78.715) 64.733,78.498 ; 64.733,78.498 ccw(c64.516,78.281) 64.516,78.588 cw(c64.516,78.281) 64.733,78.498 ; 77.494,76.327 cw(c77.494,76.02) 77.71,76.237 ccw(c77.494,76.02) 77.494,76.327 ; 77.494,76.327 ccw(c77.494,76.634) 77.71,76.417 cw(c77.494,76.634) 77.494,76.327
RD-: J1.6 R25.2 U2.13 | length 55.9
  Top Layer w0.254: v1(57.379,80.213) 57.518,80.074 61.992,80.074 U2.13@62.012,80.054 63.583,80.054 63.881,79.756 v1(63.881,78.13) ; v1(77.013,75.235) 77.013,81.021 J1.6@79.781,83.79 ; 63.881,78.437 cw(c63.574,78.437) 63.791,78.22 ccw(c63.574,78.437) 63.881,78.437 ; 63.881,78.437 ccw(c64.188,78.437) 63.971,78.22 cw(c64.188,78.437) 63.881,78.437 ; 77.013,75.541 cw(c76.706,75.541) 76.923,75.325 ccw(c76.706,75.541) 77.013,75.541 ; 77.013,75.541 ccw(c77.319,75.541) 77.103,75.325 cw(c77.319,75.541) 77.013,75.541 ; 78.697,82.706 cw(c79.781,81.622) 79.781,83.155 ccw(c79.781,81.622) 78.697,82.706 ; 78.697,82.706 ccw(c77.613,83.79) 79.146,83.79 cw(c77.613,83.79) 78.697,82.706 ; 79.131,83.139 cw(c79.781,82.489) 79.781,83.409 ccw(c79.781,82.489) 79.131,83.139 ; 79.131,83.139 ccw(c78.481,83.79) 79.4,83.79 cw(c78.481,83.79) 79.131,83.139 ; v1@57.468,80.303 ccw(c58.022,80.856) 58.022,80.074 cw(c58.022,80.856) v1@57.468,80.303
  Bottom Layer w0.254: v1(57.379,71.399) v1(57.379,80.213) ; v1(63.881,78.13) 66.777,75.235 v1(77.013,75.235) ; 57.379,71.706 cw(c57.072,71.706) 57.289,71.489 ccw(c57.072,71.706) 57.379,71.706 ; 57.379,71.706 ccw(c57.685,71.706) 57.468,71.489 cw(c57.685,71.706) 57.379,71.706 ; 57.379,79.907 cw(c57.685,79.907) 57.468,80.123 ccw(c57.685,79.907) 57.379,79.907 ; 57.379,79.907 ccw(c57.072,79.907) 57.289,80.123 cw(c57.072,79.907) 57.379,79.907 ; 64.098,77.914 cw(c64.315,78.13) 64.008,78.13 ccw(c64.315,78.13) 64.098,77.914 ; 64.098,77.914 ccw(c63.881,77.697) 63.881,78.003 cw(c63.881,77.697) 64.098,77.914 ; 76.706,75.235 cw(c76.706,74.928) 76.923,75.145 ccw(c76.706,74.928) 76.706,75.235 ; 76.706,75.235 ccw(c76.706,75.541) 76.923,75.325 cw(c76.706,75.541) 76.706,75.235
TD+: J1.1 R22.2 U2.17 | length 50.4
  Top Layer w0.254: v1(59.868,82.067) 61.999,82.067 U2.17@62.012,82.054 ; v1(63.627,74.27) v1(66.8,77.443) ; R22.2@65,71.374 v1(65,71.426) ; J1.1@82.318,77.443 J1.1@82.321,77.44 ; 60.174,82.067 cw(c60.174,82.374) 59.958,82.157 ccw(c60.174,82.374) 60.174,82.067 ; 60.174,82.067 ccw(c60.174,81.761) 59.958,81.978 cw(c60.174,81.761) 60.174,82.067 ; 63.844,74.486 cw(c63.627,74.703) 63.627,74.397 ccw(c63.627,74.703) 63.844,74.486 ; 63.844,74.486 ccw(c64.061,74.27) 63.754,74.27 cw(c64.061,74.27) 63.844,74.486 ; 66.584,77.226 cw(c66.8,77.009) 66.8,77.316 ccw(c66.8,77.009) 66.584,77.226 ; 66.584,77.226 ccw(c66.367,77.443) 66.673,77.443 cw(c66.367,77.443) 66.584,77.226
  Bottom Layer w0.254: v1(59.868,82.067) 59.868,78.029 v1(63.627,74.27) 65,72.896 v1(65,71.426) ; v1(66.8,77.443) J1.1@82.318,77.443 ; 59.868,81.761 cw(c60.174,81.761) 59.958,81.978 ccw(c60.174,81.761) 59.868,81.761 ; 59.868,81.761 ccw(c59.561,81.761) 59.778,81.978 cw(c59.561,81.761) 59.868,81.761 ; 63.41,74.486 cw(c63.193,74.27) 63.5,74.27 ccw(c63.193,74.27) 63.41,74.486 ; 63.41,74.486 ccw(c63.627,74.703) 63.627,74.397 cw(c63.627,74.703) 63.41,74.486 ; 63.844,74.053 cw(c64.061,74.27) 63.754,74.27 ccw(c64.061,74.27) 63.844,74.053 ; 63.844,74.053 ccw(c63.627,73.836) 63.627,74.143 cw(c63.627,73.836) 63.844,74.053 ; 65,71.733 cw(c64.694,71.733) 64.91,71.516 ccw(c64.694,71.733) 65,71.733 ; 65,71.733 ccw(c65.307,71.733) 65.09,71.516 cw(c65.307,71.733) 65,71.733 ; 67.107,77.443 cw(c67.107,77.75) 66.89,77.533 ccw(c67.107,77.75) 67.107,77.443 ; 67.107,77.443 ccw(c67.107,77.136) 66.89,77.353 cw(c67.107,77.136) 67.107,77.443 ; 80.78,77.443 cw(c80.78,75.899) 81.872,76.991 ccw(c80.78,75.899) 80.78,77.443 ; 80.796,77.443 ccw(c80.796,78.965) 81.872,77.889 cw(c80.796,78.965) 80.796,77.443 ; 81.393,77.443 cw(c81.393,76.512) 82.052,77.17 ccw(c81.393,76.512) 81.393,77.443 ; 81.41,77.443 ccw(c81.41,78.351) 82.052,77.709 cw(c81.41,78.351) 81.41,77.443
TD-: J1.2 R23.2 U2.16 | length 49.7
  Top Layer w0.254: v1(59.03,81.356) 60.096,81.356 60.294,81.554 U2.16@62.012,81.554 U2.16@61.992,81.534 ; v1@61.735,74.612 v1(65.786,78.664) ; J1.2@79.736,78.664 J1.2@79.781,78.71 ; 59.336,81.356 cw(c59.336,81.663) 59.119,81.446 ccw(c59.336,81.663) 59.336,81.356 ; 59.336,81.356 ccw(c59.336,81.05) 59.119,81.266 cw(c59.336,81.05) 59.336,81.356 ; 65.569,78.447 cw(c65.786,78.23) 65.786,78.537 ccw(c65.786,78.23) 65.569,78.447 ; 65.569,78.447 ccw(c65.352,78.664) 65.659,78.664 cw(c65.352,78.664) 65.569,78.447 ; v1@61.747,74.727 ccw(c61.747,74.972) 61.921,74.799 cw(c61.747,74.972) v1@61.747,74.727 ; v1@61.874,74.6 cw(c62.242,74.6) 61.982,74.86 ccw(c62.242,74.6) v1@61.874,74.6
  Bottom Layer w0.254: v1(59.03,81.356) 59.03,77.318 v1(61.747,74.6) 62.46,73.887 v1(62.46,71.374) ; v1(65.786,78.664) J1.2@79.736,78.664 ; 59.03,81.05 cw(c59.336,81.05) 59.119,81.266 ccw(c59.336,81.05) 59.03,81.05 ; 59.03,81.05 ccw(c58.723,81.05) 58.94,81.266 cw(c58.723,81.05) 59.03,81.05 ; 61.531,74.817 cw(c61.314,74.6) 61.62,74.6 ccw(c61.314,74.6) 61.531,74.817 ; 61.531,74.817 ccw(c61.747,75.033) 61.747,74.727 cw(c61.747,75.033) 61.531,74.817 ; 61.964,74.383 cw(c62.181,74.6) 61.874,74.6 ccw(c62.181,74.6) 61.964,74.383 ; 61.964,74.383 ccw(c61.747,74.166) 61.747,74.473 cw(c61.747,74.166) 61.964,74.383 ; 62.46,71.681 cw(c62.154,71.681) 62.37,71.464 ccw(c62.154,71.681) 62.46,71.681 ; 62.46,71.681 ccw(c62.767,71.681) 62.55,71.464 cw(c62.767,71.681) 62.46,71.681 ; 66.093,78.664 cw(c66.093,78.97) 65.876,78.754 ccw(c66.093,78.97) 66.093,78.664 ; 66.093,78.664 ccw(c66.093,78.357) 65.876,78.574 cw(c66.093,78.357) 66.093,78.664 ; 78.138,78.664 ccw(c78.138,80.353) 79.332,79.159 cw(c78.138,80.353) 78.138,78.664 ; 78.359,78.664 cw(c78.359,77.287) 79.332,78.261 ccw(c78.359,77.287) 78.359,78.664 ; 78.751,78.664 ccw(c78.751,79.74) 79.512,78.979 cw(c78.751,79.74) 78.751,78.664 ; 78.972,78.664 cw(c78.972,77.9) 79.512,78.44 ccw(c78.972,77.9) 78.972,78.664
UI: OPIN.2 R42.1 | length 16.2
  Top Layer w0.254: R42.1@3.556,49.274 3.556,46.838 4.064,46.33 OPIN.2@4.064,44.704 ; 3.556,48.048 cw(c4.782,48.048) 3.915,48.915 ccw(c4.782,48.048) 3.556,48.048 ; 3.556,48.048 ccw(c2.33,48.048) 3.197,48.915 cw(c2.33,48.048) 3.556,48.048 ; 4.064,45.595 cw(c3.173,45.595) 3.803,44.965 ccw(c3.173,45.595) 4.064,45.595 ; 4.064,45.595 ccw(c4.955,45.595) 4.325,44.965 cw(c4.955,45.595) 4.064,45.595 ; 4.064,46.208 cw(c2.56,46.208) 3.623,45.145 ccw(c2.56,46.208) 4.064,46.208 ; 4.064,46.208 ccw(c5.568,46.208) 4.505,45.145 cw(c5.568,46.208) 4.064,46.208
UO: C46.2 OPIN.1 R46.1 U11.1 | length 52.3
  Top Layer w0.254: R46.1@1.524,62.711 2.796,63.983 5.561,63.983 C46.2@6.831,62.713 ; U11.1@6.833,59.766 C46.2@6.833,62.711 ; 6.833,60.226 cw(c6.373,60.226) 6.698,59.901 ccw(c6.373,60.226) 6.833,60.226 ; 6.833,60.226 ccw(c7.293,60.226) 6.967,59.901 cw(c7.293,60.226) 6.833,60.226 ; R46.1@1.651,62.662 cw(c2.076,62.662) 1.776,62.963 ccw(c2.076,62.662) R46.1@1.651,62.662 ; R46.1@1.651,63.219 ccw(c1.651,64.139) 2.301,63.488 cw(c1.651,64.139) R46.1@1.651,63.219 ; R46.1@1.905,62.711 cw(c2.825,62.711) 2.174,63.361 ccw(c2.825,62.711) R46.1@1.905,62.711 ; R46.1@2.159,62.711 cw(c3.692,62.711) 2.608,63.795 ccw(c3.692,62.711) R46.1@2.159,62.711 ; 5.747,63.797 ccw(c6.831,64.881) 6.831,63.348 cw(c6.831,64.881) 5.747,63.797 ; 6.054,63.49 cw(c5.403,62.84) 6.323,62.84 ccw(c5.403,62.84) 6.054,63.49 ; 6.181,63.363 ccw(c6.831,64.013) 6.831,63.094 cw(c6.831,64.013) 6.181,63.363 ; C46.2@6.472,62.226 cw(c5.601,61.355) 6.833,61.355 ccw(c5.601,61.355) C46.2@6.472,62.226 ; 6.833,61.363 cw(c8.053,61.363) 7.19,62.226 ccw(c8.053,61.363) 6.833,61.363
  Bottom Layer w0.254: OPIN.1@1.524,44.704 v1(1.524,62.662) ; 1.524,45.595 cw(c0.633,45.595) 1.263,44.965 ccw(c0.633,45.595) 1.524,45.595 ; 1.524,45.595 ccw(c2.415,45.595) 1.785,44.965 cw(c2.415,45.595) 1.524,45.595 ; 1.524,46.208 cw(c0.02,46.208) 1.083,45.145 ccw(c0.02,46.208) 1.524,46.208 ; 1.524,46.208 ccw(c3.028,46.208) 1.965,45.145 cw(c3.028,46.208) 1.524,46.208 ; 1.524,62.355 cw(c1.831,62.355) 1.614,62.572 ccw(c1.831,62.355) 1.524,62.355 ; 1.524,62.355 ccw(c1.217,62.355) 1.434,62.572 cw(c1.217,62.355) 1.524,62.355
VCC5: 2.4'/2.8'LCD.28 C8.1 C9.1 C36.2 C42.2 C43.2 C47.1 C48.1 P1.1 P1.3 P1.5 P2.1 P2.3 U4.3 U8.3 U10.16 U11.8 USB_232.1 USB_OTG.1 | length 308.6
  Top Layer w0.381: C42.2@86.841,15.951 88.06,14.732 USB_232.1@90.424,14.732 ; C42.2@86.892,15.43 cw(c86.892,14.296) 87.694,15.098 ccw(c86.892,14.296) C42.2@86.892,15.43 ; C42.2@87.336,15.875 ccw(c88.348,15.875) 87.633,15.16 cw(c88.348,15.875) C42.2@87.336,15.875
  Top Layer w0.508: v1(9.704,59.766) U11.8@12.533,59.766 ; P1.3@15.24,71.12 16.51,72.39 19.99,72.39 21.184,71.196 v1(29.21,71.196) ; v1(29.21,64.16) v1(36.703,64.16) ; 2.4'/2.8'LCD.28@31.267,3.734 32.512,4.978 v1(65.583,4.978) ; v1(36.703,71.73) 40.005,71.73 41.859,73.584 v1(45.72,73.584) ; v1(47.676,73.584) v1(50.495,73.584) ; v1(55.855,73.584) 70.028,73.584 P2.1@70.104,73.66 ; P2.3@70.104,71.12 71.349,69.875 79.426,69.875 v1(80.594,68.707) ; v1(77.775,45.085) C36.2@79.072,45.085 U4.3@81.915,45.085 ; v1(79.197,19.101) 80.594,19.101 81.788,17.907 C43.2@83.691,17.907 ; C8.1@87.808,55.956 v1(87.808,57.633) ; v1(87.859,61.29) 87.859,63.83 88.544,64.516 USB_OTG.1@90.424,64.516 ; 16.087,71.967 cw(c15.24,72.813) 15.24,71.616 ccw(c15.24,72.813) 16.087,71.967 ; 16.087,71.967 ccw(c16.933,71.12) 15.736,71.12 cw(c16.933,71.12) 16.087,71.967 ; 32.178,4.644 cw(c31.267,5.555) 31.267,4.267 ccw(c31.267,5.555) 32.178,4.644 ; 32.178,4.644 ccw(c33.089,3.734) 31.801,3.734 cw(c33.089,3.734) 32.178,4.644 ; 70.951,70.273 cw(c71.797,71.12) 70.6,71.12 ccw(c71.797,71.12) 70.951,70.273 ; 70.951,70.273 ccw(c70.104,69.427) 70.104,70.624 cw(c70.104,69.427) 70.951,70.273 ; 78.152,45.085 cw(c78.152,44.165) 78.802,44.816 ccw(c78.152,44.165) 78.152,45.085 ; 78.152,45.085 ccw(c78.152,46.005) 78.802,45.354 cw(c78.152,46.005) 78.152,45.085 ; 79.992,45.085 cw(c79.992,46.005) 79.341,45.354 ccw(c79.992,46.005) 79.992,45.085 ; 79.992,45.085 ccw(c79.992,44.165) 79.341,44.816 cw(c79.992,44.165) 79.992,45.085 ; 82.772,17.907 cw(c82.772,16.987) 83.422,17.638 ccw(c82.772,16.987) 82.772,17.907 ; 82.772,17.907 ccw(c82.772,18.827) 83.422,18.176 cw(c82.772,18.827) 82.772,17.907 ; 68.723,73.584 ccw(c68.723,75.041) 69.753,74.011 cw(c68.723,75.041) 68.723,73.584 ; 69.091,73.584 cw(c69.091,72.647) 69.753,73.309 ccw(c69.091,72.647) 69.091,73.584 ; C8.1@87.463,56.301 ccw(c86.629,57.135) 87.808,57.135 cw(c86.629,57.135) C8.1@87.463,56.301 ; v1@87.808,57.503 ccw(c89.507,57.503) 88.305,56.301 cw(c89.507,57.503) v1@87.808,57.503
  Top Layer w1.016: v1(79.045,55.88) U8.3@82.805,55.88 ; v1(79.07,51.257) 79.072,51.256 C36.2@79.072,45.085 ; U8.3@82.806,55.881 C8.1@87.884,55.88 ; C43.2@83.702,17.896 U10.16@83.702,15.951 86.841,15.951 C42.2@86.892,16.002 ; C8.1@87.884,55.88 C9.1@93.474,55.88
  Bottom Layer w0.508: P1.5@15.24,68.58 14.021,67.361 14.021,65.126 13.233,64.338 11.278,64.338 10.846,63.906 ; v1(29.21,64.16) v1(29.21,71.196) ; v1(36.703,64.16) v1(36.703,71.73) ; v1(45.72,73.584) v1(47.676,73.584) ; v1(50.495,73.584) v1(55.855,73.584) ; v1(65.583,4.978) 65.583,10.668 67.513,12.598 67.513,18.313 68.301,19.101 v1(79.197,19.101) 79.197,35.585 77.775,37.008 v1(77.775,45.085) ; v1(87.808,57.633) 87.859,57.683 v1(87.859,61.29) ; v1(9.704,59.766) cw(c10.199,59.766) 9.849,60.116 ccw(c10.199,59.766) v1(9.704,59.766) ; v1(9.704,59.766) 9.704,59.971 10.846,61.112 C48.1@10.846,62.586 10.846,63.906 ; 10.846,61.147 cw(c12.285,61.147) 11.267,62.164 ccw(c12.285,61.147) 10.846,61.147 ; 10.846,61.147 ccw(c9.407,61.147) 10.424,62.164 cw(c9.407,61.147) 10.846,61.147 ; 10.846,63.906 cw(c9.68,63.906) 10.451,63.033 ccw(c9.68,63.906) 10.846,63.906 ; 10.846,63.906 ccw(c12.011,63.906) 11.24,63.033 cw(c12.011,63.906) 10.846,63.906 ; 14.393,67.733 cw(c15.24,66.887) 15.24,68.084 ccw(c15.24,66.887) 14.393,67.733 ; 14.393,67.733 ccw(c13.547,68.58) 14.744,68.58 cw(c13.547,68.58) 14.393,67.733 ; C47.1@9.704,60.274 ccw(c9.704,61.006) 10.222,60.489 cw(c9.704,61.006) C47.1@9.704,60.274 ; C47.1@10.085,59.893 cw(c11.193,59.893) 10.41,60.676 ccw(c11.193,59.893) C47.1@10.085,59.893
  Bottom Layer w1.016: P1.5@15.24,68.58 P1.3@15.24,71.12 P1.1@15.24,73.66 ; P2.3@70.104,71.12 P2.1@70.104,73.66 ; v1(79.07,51.257) 79.07,55.855 v1(79.045,55.88) 79.045,62.738 80.518,64.211 v1@80.518,68.707
VDDA: C19.1 C34.1 C35.1 R31.2 U1.21 U1.22 | length 97.3
  Top Layer w0.254: v1(27.584,43.561) 29.896,43.561 30.556,42.901 C19.1@30.556,41.454 32.002,41.454 32.36,41.097 v1(34.569,41.097) ; U1.22@36.988,42.449 U1.21@37.342,42.802 38.506,41.638 v1(38.506,41.097) ; 27.891,43.561 cw(c27.891,43.868) 27.674,43.651 ccw(c27.891,43.868) 27.891,43.561 ; 27.891,43.561 ccw(c27.891,43.254) 27.674,43.471 cw(c27.891,43.254) 27.891,43.561 ; 30.556,42.681 cw(c29.33,42.681) 30.197,41.814 ccw(c29.33,42.681) 30.556,42.681 ; 30.556,42.681 ccw(c31.783,42.681) 30.915,41.814 cw(c31.783,42.681) 30.556,42.681 ; 31.91,41.454 cw(c31.91,42.681) 31.042,41.814 ccw(c31.91,42.681) 31.91,41.454 ; 31.91,41.454 ccw(c31.91,40.228) 31.042,41.095 cw(c31.91,40.228) 31.91,41.454 ; 34.263,41.097 cw(c34.263,40.791) 34.48,41.007 ccw(c34.263,40.791) 34.263,41.097 ; 34.263,41.097 ccw(c34.263,41.404) 34.48,41.187 cw(c34.263,41.404) 34.263,41.097 ; 38.506,41.404 cw(c38.2,41.404) 38.417,41.187 ccw(c38.2,41.404) 38.506,41.404 ; 38.506,41.404 ccw(c38.813,41.404) 38.596,41.187 cw(c38.813,41.404) 38.506,41.404
  Bottom Layer w0.254: C34.1@27.254,84.834 26.086,83.666 26.086,52.197 24.486,50.597 24.486,44.196 25.121,43.561 v1(27.584,43.561) ; v1(34.569,41.097) v1(38.506,41.097) ; 27.278,43.561 cw(c27.278,43.254) 27.495,43.471 ccw(c27.278,43.254) 27.278,43.561 ; 27.278,43.561 ccw(c27.278,43.868) 27.495,43.651 cw(c27.278,43.868) 27.278,43.561 ; 34.876,41.097 cw(c34.876,41.404) 34.659,41.187 ccw(c34.876,41.404) 34.876,41.097 ; 34.876,41.097 ccw(c34.876,40.791) 34.659,41.007 cw(c34.876,40.791) 34.876,41.097 ; 38.2,41.097 cw(c38.2,40.791) 38.417,41.007 ccw(c38.2,40.791) 38.2,41.097 ; 38.2,41.097 ccw(c38.2,41.404) 38.417,41.187 cw(c38.2,41.404) 38.2,41.097 ; 26.17,83.75 ccw(c25.086,84.834) 26.619,84.834 cw(c25.086,84.834) 26.17,83.75 ; 26.477,84.057 cw(c27.127,83.407) 27.127,84.326 ccw(c27.127,83.407) 26.477,84.057 ; 26.604,84.184 ccw(c25.953,84.834) 26.873,84.834 cw(c25.953,84.834) 26.604,84.184
  Bottom Layer w0.508: C35.1@27.254,87.882 C34.1@27.254,84.834 R31.2@30.556,84.834 ; 27.254,85.754 cw(c26.334,85.754) 26.985,85.104 ccw(c26.334,85.754) 27.254,85.754 ; 27.254,85.754 ccw(c28.174,85.754) 27.524,85.104 cw(c28.174,85.754) 27.254,85.754 ; 27.254,86.963 cw(c28.174,86.963) 27.524,87.613 ccw(c28.174,86.963) 27.254,86.963 ; 27.254,86.963 ccw(c26.334,86.963) 26.985,87.613 cw(c26.334,86.963) 27.254,86.963 ; 28.301,84.834 cw(c28.301,85.754) 27.651,85.104 ccw(c28.301,85.754) 28.301,84.834 ; 28.301,84.834 ccw(c28.301,83.915) 27.651,84.565 cw(c28.301,83.915) 28.301,84.834 ; 29.509,84.834 cw(c29.509,83.915) 30.16,84.565 ccw(c29.509,83.915) 29.509,84.834 ; 29.509,84.834 ccw(c29.509,85.754) 30.16,85.104 cw(c29.509,85.754) 29.509,84.834
pads on no net: 2.4'/2.8'LCD. 2.4'/2.8'LCD.32 J1.7 JTAG.3 JTAG.5 JTAG.11 JTAG.13 JTAG.17 JTAG.19 TF_CARD.0 TF_CARD.9 U1.6 U2.1 U2.5 U2.6 U2.8 U2.9 U2.10 U2.11 U2.12 U2.33 U2.38 U2.40 U2.41 U2.42 U2.45 U2.46 U4.5 U10.9 U10.10 U10.11 U10.12 U10.13 U10.14 U10.15 U11.5 U11.6 U11.7 USB_232.6 USB_232.7 USB_232.8 USB_232.9 USB_232.MH1 USB_232.MH2 USB_OTG.6 USB_OTG.7 USB_OTG.8 USB_OTG.9 USB_OTG.MH1 USB_OTG.MH2 Y1. Y2. Y3. Y4.1

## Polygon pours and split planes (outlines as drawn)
GND on Bottom Layer "Top Layer-No Net" (solid, remove dead copper, pour order 1001): -0.559,100.228 -0.533,100.203 101.752,100.203 101.752,-0.432 101.803,-0.483 101.575,-0.254 -0.178,-0.254 -0.178,99.847 -0.559,100.228
GND on Top Layer "Top Layer-No Net 1" (solid, remove dead copper): -0.229,100.228 -0.076,100.076 100.559,100.076 100.559,-0.254 100.635,-0.33 100.482,-0.178 0,-0.178 0,100 -0.229,100.228

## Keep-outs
Keep-Out Layer:
  lines w0.254: 0,4.994 0,95.199 ; 0,5.055 ccw(c5.011,5.025) 4.98,0.014 ; 0,94.996 cw(c5.011,94.965) 5.041,99.976 ; 4.801,100 95.25,100 ; 4.994,0 95.098,0 ; 94.971,0 ccw(c95,5.011) 100.011,4.98 ; 95.02,100.011 cw(c94.989,95) 100,94.971 ; 100,4.902 100,95.25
